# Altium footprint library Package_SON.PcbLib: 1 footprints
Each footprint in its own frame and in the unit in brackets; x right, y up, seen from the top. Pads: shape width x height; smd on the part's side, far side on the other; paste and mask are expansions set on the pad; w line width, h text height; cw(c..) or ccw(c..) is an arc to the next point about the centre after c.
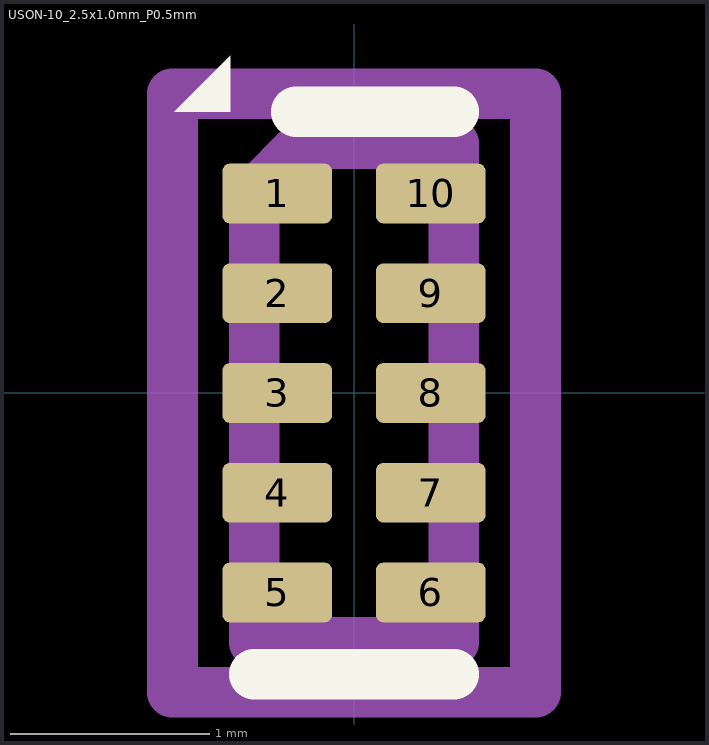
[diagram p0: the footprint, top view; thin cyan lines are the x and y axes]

## USON-10_2.5x1.0mm_P0.5mm [mm]
pads (10):
  rrect25% 0.55x0.3 smd: 1(-0.385,1) 2(-0.385,0.5) 3(-0.385,0) 4(-0.385,-0.5) 5(-0.385,-1) 6(0.385,-1) 7(0.385,-0.5) 8(0.385,0) 9(0.385,0.5) 10(0.385,1)
F.SilkS:
  region: -0.62,1.41 -0.9,1.41 -0.62,1.69
  lines w0.254: -0.5,-1.41 0.5,-1.41 ; -0.29,1.41 0.5,1.41
F.CrtYd:
  lines w0.254: -0.91,-1.5 -0.91,1.5 0.91,1.5 0.91,-1.5 -0.91,-1.5
F.Fab:
  lines w0.254: -0.5,-1.25 -0.5,1 -0.25,1.25 0.5,1.25 0.5,-1.25 -0.5,-1.25
  text "'.Designator'" at 0.48,-2.243 h0.55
